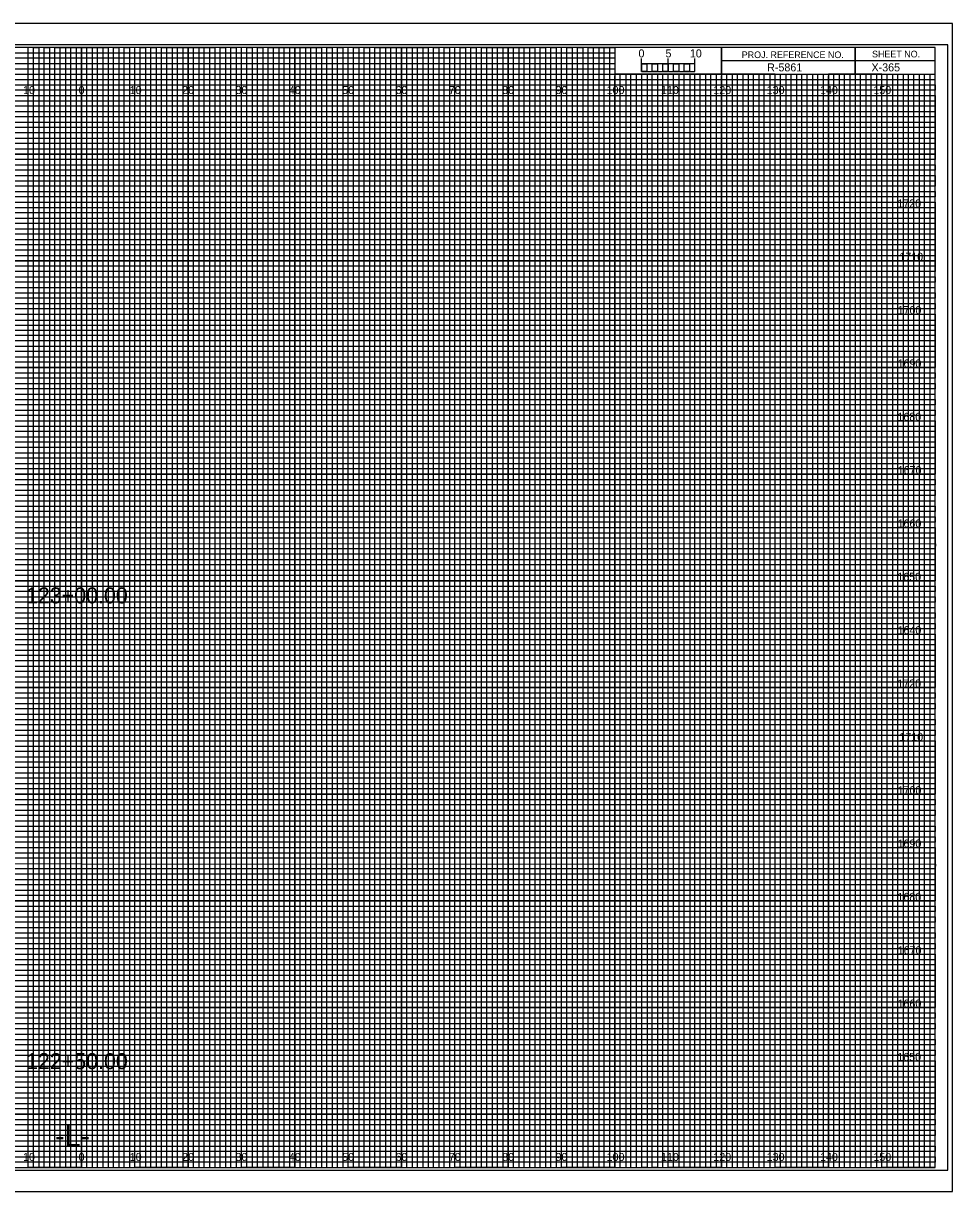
# Model space of a CAD drawing. Extents: x -13 to 323, y -5 to 2414.
# Drawn here: x 149.1 to 323.3, y 215.5 to 434.5 of the extents above; entities that cross this region are included whole.
import ezdxf

# ---------------------------------------------------------------- set-up
doc = ezdxf.new("R2010")
doc.units = 0
for name, color, linetype in [('Prop XS Alignment Label', 7, 'Continuous'), ('Prop XS Bar Scale Labels', 7, 'Continuous'), ('Prop XS Elevation Labels', 7, 'Continuous'), ('Prop XS Offset Labels', 7, 'Continuous'), ('Prop XS Project Number', 7, 'Continuous'), ('Prop XS Sheet Number', 7, 'Continuous'), ('Prop XS Station Labels', 7, 'Continuous'), ('Sheet Cross Section CELL', 7, 'Continuous'), ('Sheet Cross Section Grid Major CELL', 7, 'Continuous'), ('Sheet Cross Section Grid Middle CELL', 7, 'Continuous'), ('Sheet Cross Section Grid Minor 1 CELL', 7, 'Continuous'), ('Sheet Cross Section Grid Minor 2 CELL', 7, 'Continuous'), ('Sheet Cross Section Scale CELL', 7, 'Continuous'), ('Sheet Cutting Line CELL', 7, 'Continuous'), ('Sheet DOT Grid CELL', 7, 'Continuous'), ('Sheet Plot Border Inside CELL', 7, 'Continuous'), ('Sheet Plot Border Outside CELL', 7, 'Continuous')]:
    doc.layers.add(name, color=color, linetype=linetype)

msp = doc.modelspace()

# ---------------------------------------------------------------- linework, layer by layer
at = {"layer": 'Sheet Cross Section CELL'}
for p, q in [((305, 430), (305, 425)), ((305, 425), (305, 430)), ((280, 427.5), (280, 425)), ((320, 427.49), (280, 427.49)), ((280, 425), (320, 425))]:
    msp.add_line(p, q, dxfattribs=at)
for points in [[(320, 430), (0, 430), (0, 220), (320, 220)], [(280, 430), (260, 430), (260, 425.03), (280, 425.03)], [(320, 430), (280, 430), (280, 425), (320, 425)]]:
    msp.add_lwpolyline(points, close=True, dxfattribs=at)
at = {"layer": 'Sheet Cross Section Grid Major CELL'}
for p, q in [((150, 430), (140, 430)), ((150, 220), (150, 430)), ((170, 430), (160, 430)), ((160, 430), (160, 220)), ((170, 220), (170, 430)), ((190, 430), (180, 430)), ((180, 430), (180, 220)), ((190, 220), (190, 430)), ((210, 430), (200, 430)), ((200, 430), (200, 220)), ((210, 220), (210, 430)), ((230, 430), (220, 430)), ((220, 430), (220, 220)), ((230, 220), (230, 430)), ((250, 430), (240, 430)), ((240, 430), (240, 220)), ((250, 220), (250, 430)), ((260, 430), (260, 220)), ((270, 220), (270, 425)), ((290, 425), (280, 425)), ((280, 425), (280, 220)), ((290, 220), (290, 425)), ((310, 425), (300, 425)), ((300, 425), (300, 220)), ((310, 220), (310, 425)), ((160, 220), (150, 220)), ((180, 220), (170, 220)), ((200, 220), (190, 220)), ((220, 220), (210, 220)), ((240, 220), (230, 220)), ((260, 220), (250, 220)), ((280, 220), (270, 220)), ((300, 220), (290, 220)), ((320, 220), (310, 220)), ((320, 220), (320, 220))]:
    msp.add_line(p, q, dxfattribs=at)
for points in [[(0, 420), (320, 420), (320, 410), (0, 410)], [(0, 400), (320, 400), (320, 390), (0, 390)], [(0, 380), (320, 380), (320, 370), (0, 370)], [(0, 360), (320, 360), (320, 350), (0, 350)], [(0, 340), (320, 340), (320, 330), (0, 330)], [(0, 320), (320, 320), (320, 310), (0, 310)], [(0, 300), (320, 300), (320, 290), (0, 290)], [(0, 280), (320, 280), (320, 270), (0, 270)], [(0, 260), (320, 260), (320, 250), (0, 250)], [(0, 240), (320, 240), (320, 230), (0, 230)]]:
    msp.add_lwpolyline(points, dxfattribs=at)
at = {"layer": 'Sheet Cross Section Grid Middle CELL'}
for points in [[(145, 220), (155, 220), (155, 430), (165, 430), (165, 220), (175, 220), (175, 430), (185, 430), (185, 220), (195, 220), (195, 430), (205, 430), (205, 220), (215, 220), (215, 430), (225, 430), (225, 220), (235, 220), (235, 430), (245, 430), (245, 220), (255, 220), (255, 430), (259.93, 430), (260, 430), (260, 425), (264.99, 425), (264.99, 220), (275, 220), (275, 425), (285, 425), (285, 220), (295, 220), (295, 425), (305, 425), (305, 220), (315, 220), (315, 425)], [(0, 425), (275, 425)], [(0, 405), (320, 405), (320, 415), (0, 415)], [(0, 385), (320, 385), (320, 395), (0, 395)], [(0, 365), (320, 365), (320, 375), (0, 375)], [(0, 345), (320, 345), (320, 355), (0, 355)], [(0, 325), (320, 325), (320, 335), (0, 335)], [(0, 305), (320, 305), (320, 315), (0, 315)], [(0, 285), (320, 285), (320, 295), (0, 295)], [(0, 265), (320, 265), (320, 275), (0, 275)], [(0, 245), (320, 245), (320, 255), (0, 255)], [(0, 225), (320, 225), (320, 235), (0, 235)]]:
    msp.add_lwpolyline(points, dxfattribs=at)
at = {"layer": 'Sheet Cross Section Grid Minor 1 CELL'}
for p, q in [((0, 429), (260, 429)), ((260, 427.98), (0, 427.98)), ((260, 429), (260, 427.98)), ((0, 427), (260, 427)), ((260, 425.89), (0, 425.89)), ((260, 427), (260, 425.89)), ((0, 424), (320, 424))]:
    msp.add_line(p, q, dxfattribs=at)
for points in [[(0, 423), (270, 423), (320, 423), (320, 422), (0, 422)], [(0, 421), (320, 421), (320, 419), (0, 419)], [(0, 418), (320, 418), (320, 417), (0, 416.98)], [(0, 416), (320, 416), (320, 414), (0, 414)], [(0, 413), (320, 413), (320, 412), (0, 412)], [(0, 411), (320, 411), (320, 409), (0, 409)], [(0, 408), (320, 408), (320, 407), (0, 407)], [(0, 406), (320, 406), (320, 404), (0, 404)], [(0, 403), (320, 403), (320, 402), (0, 402)], [(0, 401), (320, 401), (320, 399), (0, 399)], [(0, 398), (320, 398), (320, 397), (0, 397)], [(0, 396), (320, 396), (320, 393.95), (320, 393), (320, 392), (0, 392)], [(0, 394), (320, 394), (320, 393), (0, 393)], [(0, 391), (320, 391), (320, 389), (0, 389.03)], [(0, 389.03), (320, 389), (320, 388), (0, 388)], [(0, 387), (320, 387), (320, 386), (0, 386)], [(0, 384), (320, 384), (320, 383), (0, 383)], [(0, 382), (320, 382), (320, 381), (0, 381)], [(-0.07, 378.89), (320, 378.89), (320, 377.88), (-0.07, 377.88)], [(0, 377), (320, 377), (320, 376), (0, 376)], [(0, 374), (320, 374), (320, 373), (0, 373)], [(0, 372), (320, 372), (320, 371), (0, 371)], [(0, 369), (320, 369), (320, 368), (0, 368)], [(0, 367), (320, 367), (320, 366), (0, 366)], [(0, 364), (320, 364), (320, 363), (0, 363)], [(0, 362), (320, 362), (320, 361), (0, 361)], [(0, 359), (320, 359), (319.99, 357.98), (0, 358)], [(0, 357), (320, 357), (320, 356), (0, 356)], [(0, 354), (320, 354), (320, 353), (0, 353)], [(0, 352), (320, 352), (320, 351), (0, 351)], [(0, 349), (320, 349), (320, 348), (0, 348)], [(0, 347), (320, 347), (320, 346), (0, 346)], [(0, 344), (320, 344), (320, 343), (0, 343)], [(0, 342), (320, 342), (320, 341), (0, 341)], [(0, 339), (320, 339), (320, 338), (0, 338)], [(0, 336.99), (320.07, 336.91), (320, 336), (0, 336)], [(0, 334), (320, 334), (320, 333), (0, 333)], [(0, 332), (320, 332), (320, 331), (0, 331)], [(0, 329), (320, 329), (320, 328), (0, 328)], [(0, 327), (320, 327), (320, 326), (0, 326)], [(0, 324), (320, 324), (320, 323), (0, 323)], [(0, 322), (320, 322), (320, 321), (0, 321)], [(0, 319), (320, 319), (320, 318), (0, 318)], [(0, 317), (320, 317), (320, 316), (0, 316)], [(0, 314), (320, 314), (320, 313), (0, 313)], [(0, 312), (320, 312), (320, 311), (0, 311)], [(0, 309), (320, 309), (320, 308), (0, 308)], [(0, 307), (320, 307), (320, 306), (0, 306)], [(0, 304), (320, 304), (320, 303), (0, 303)], [(0, 302), (320, 302), (320, 301), (0, 301)], [(0, 299), (320, 299), (319.99, 297.98), (0, 298)], [(0, 297), (320, 297), (320, 296), (0, 296)], [(0, 294), (320, 294), (320, 293), (0, 293)], [(0, 292), (320, 292), (320, 291), (0, 291)], [(0, 289), (320, 289), (320, 288), (0, 288)], [(0, 287), (320, 287), (320, 286), (0, 286)], [(0, 284), (320, 284), (320, 283), (0, 283)], [(0, 282), (320, 282), (320, 281), (0, 281)], [(0, 279), (320, 279), (320, 278), (0, 278)], [(0, 276.99), (320.07, 276.91), (320, 276), (0, 276)], [(0, 274), (320, 274), (320, 273), (0, 273)], [(0, 272), (320, 272), (320, 271), (0, 271)], [(0, 269), (320, 269), (320, 268), (0, 268)], [(0, 267), (320, 267), (320, 266), (0, 266)], [(0, 264), (320, 264), (320, 263), (0, 263)], [(0, 262), (320, 262), (320, 261), (0, 261)], [(0, 259), (320, 259), (320, 258), (0, 258)], [(0, 257), (320, 257), (320, 256), (0, 256)], [(0, 254), (320, 254), (320, 253), (0, 253)], [(0, 252), (320, 252), (320, 251), (0, 251)], [(0, 249), (320, 249), (320, 248), (0, 248)], [(0, 247), (320, 247), (320, 246), (0, 246)], [(0, 244), (320, 244), (320, 243), (0, 243)], [(0, 242), (320, 242), (320, 241), (0, 241)], [(0, 239), (320, 239), (320, 238), (0, 238)], [(0, 237), (320, 237), (320, 236), (0, 236)], [(0, 234), (320, 234), (320, 233), (0, 233)], [(0, 232), (320, 232), (320, 231), (0, 231)], [(0, 229), (320, 229), (320, 228), (0, 228)], [(0, 227), (320, 227), (320, 226), (0, 226)], [(0, 224), (320, 224), (320, 223), (0, 223)], [(0, 222), (320, 222), (320, 221), (0, 221)]]:
    msp.add_lwpolyline(points, dxfattribs=at)
at = {"layer": 'Sheet Cross Section Grid Minor 2 CELL'}
for p, q in [((267, 425), (266.01, 425)), ((266.01, 425), (266.01, 220)), ((267, 220), (267, 425)), ((269, 425), (268, 425)), ((268, 425), (268, 220)), ((269, 220), (269, 425)), ((266.01, 220), (265, 220)), ((268, 220), (267, 220))]:
    msp.add_line(p, q, dxfattribs=at)
for points in [[(150, 220), (151, 220), (151, 430), (152, 430), (152, 220)], [(152, 220), (153, 220), (153, 430), (154, 430), (154, 220)], [(155, 220), (156, 220), (156, 430), (157, 430), (157, 220)], [(157, 220), (158, 220), (158, 430), (159, 430), (159, 220)], [(160, 220), (161, 220), (161, 430), (162, 430), (162, 220)], [(162, 220), (163, 220), (163, 430), (164, 430), (164, 220)], [(165, 220), (166, 220), (166, 430), (167, 430), (167, 220)], [(167, 220), (168, 220), (168, 430), (169, 430), (169, 220)], [(170, 220), (171, 220), (171, 430), (172, 430), (172, 220)], [(172, 220), (173, 220), (173, 430), (174, 430), (174, 220)], [(175, 220), (176, 220), (176, 430), (177, 430), (177, 220)], [(177, 220), (178, 220), (178, 430), (179, 430), (179, 220)], [(180, 220), (181, 220), (181, 430), (182, 430), (182, 220)], [(182, 220), (183, 220), (183, 430), (184, 430), (184, 220)], [(185, 220), (186, 220), (186, 430), (187, 430), (187, 220)], [(187, 220), (188, 220), (188, 430), (189, 430), (189, 220)], [(190, 220), (191, 220), (191, 430), (192, 430), (192, 220)], [(192, 220), (193, 220), (193, 430), (194, 430), (194, 220)], [(195, 220), (196, 220), (196, 430), (197, 430), (197, 220)], [(197, 220), (198, 220), (198, 430), (199, 430), (199, 220)], [(200, 220), (201, 220), (201, 430), (202, 430), (202, 220)], [(202, 220), (203, 220), (203, 430), (204, 430), (204, 220)], [(205, 220), (206, 220), (206, 430), (207, 430), (207, 220)], [(207, 220), (208, 220), (208, 430), (209, 430), (209, 220)], [(210, 220), (211, 220), (211, 430), (212, 430), (212, 220)], [(212, 220), (213, 220), (213, 430), (214, 430), (214, 220)], [(215, 220), (216, 220), (216, 430), (217, 430), (217, 220)], [(217, 220), (218, 220), (218, 430), (219, 430), (219, 220)], [(220, 220), (221, 220), (221, 430), (222, 430), (222, 220)], [(222, 220), (223, 220), (223, 430), (224, 430), (224, 220)], [(225, 220), (226, 220), (226, 430), (227, 430), (227, 220)], [(227, 220), (228, 220), (228, 430), (229, 430), (229, 220)], [(230, 220), (231, 220), (231, 430), (232, 430), (232, 220)], [(232, 220), (233, 220), (233, 430), (234, 430), (234, 220)], [(235, 220), (236, 220), (236, 430), (237, 430), (237, 220)], [(237, 220), (238, 220), (238, 430), (239, 430), (239, 220)], [(240, 220), (241, 220), (241, 430), (242, 430), (242, 220)], [(242, 220), (243, 220), (243, 430), (244, 430), (244, 220)], [(245, 220), (246, 220), (246, 430), (247, 430), (247, 220)], [(247, 220), (248, 220), (248, 430), (249, 430), (249, 220)], [(250, 220), (251, 220), (251, 430), (252, 430), (252, 220)], [(252, 220), (253, 220), (253, 430), (254, 430), (254, 220)], [(255, 220), (256, 220), (256, 430), (257, 430), (257, 220)], [(257, 220), (258, 220), (258, 430), (259, 430), (259, 220)], [(260, 220), (261, 220), (261, 425), (262.02, 425), (262.02, 220)], [(262, 220), (263, 220), (263, 425), (263.99, 425), (263.99, 220)], [(270, 220), (270.98, 220), (270.98, 425), (272, 425), (272, 220)], [(272, 220), (273, 220), (273, 425), (274.05, 425), (274.05, 220)], [(275, 220), (276, 220), (276, 425), (277, 425), (277, 220)], [(277, 220), (278, 220), (278, 425), (279, 425), (279, 220)], [(280, 220), (281, 220), (281, 425), (282, 425), (282, 220)], [(282, 220), (283, 220), (283, 425), (284, 425), (284, 220)], [(285, 220), (286, 220), (286, 425), (287, 425), (287, 220)], [(287, 220), (288, 220), (288, 425), (289, 425), (289, 220)], [(290, 220), (291, 220), (291, 425), (292, 425), (292, 220)], [(292, 220), (293, 220), (293, 425), (294, 425), (294, 220)], [(295, 220), (296, 220), (296, 425), (297, 425), (297, 220)], [(297, 220), (298, 220), (298, 425), (299, 425), (299, 220)], [(300, 220), (301, 220), (301, 425), (302, 425), (302, 220)], [(302, 220), (303, 220), (303, 425), (304, 425), (304, 220)], [(305, 220), (306, 220), (306, 425), (307, 425), (307, 220)], [(307, 220), (308, 220), (308, 425), (309, 425), (309, 220)], [(310, 220), (311, 220), (311, 425), (312, 425), (312, 220)], [(312, 220), (313, 220), (313, 425), (314, 425), (314, 220)], [(315, 220), (316, 220), (316, 425), (317, 425), (317, 220)], [(317, 220), (318, 220), (318, 425), (319, 425), (319, 220)]]:
    msp.add_lwpolyline(points, dxfattribs=at)
at = {"layer": 'Sheet Cross Section Scale CELL'}
for p, q in [((265, 425.49), (265, 427.9)), ((265, 426.9), (265, 427.9)), ((270, 425.49), (270, 427.9)), ((275, 425.49), (275, 427.9)), ((275, 426.9), (275, 427.9))]:
    msp.add_line(p, q, dxfattribs=at)
for points in [[(275, 426.9), (265, 426.9), (265, 425.49), (275, 425.49)], [(265, 426.9), (266, 426.9), (266, 425.49), (265, 425.49)], [(267, 426.9), (268, 426.9), (268, 425.49), (267, 425.49)], [(269, 426.9), (270, 426.9), (270, 425.49), (269, 425.49)], [(271, 426.9), (272, 426.9), (272, 425.49), (271, 425.49)], [(273, 426.9), (274, 426.9), (274, 425.49), (273, 425.49)]]:
    msp.add_lwpolyline(points, close=True, dxfattribs=at)
at = {"layer": 'Sheet Cutting Line CELL'}
for p, q in [((323.3, 434.5), (-13.4, 434.5)), ((-13.4, 215.5), (323.3, 215.5))]:
    msp.add_line(p, q, dxfattribs=at)
at = {"layer": 'Sheet DOT Grid CELL'}
for p, q in [((150, 220), (150, 430)), ((160, 220), (160, 430)), ((170, 220), (170, 430)), ((180, 220), (180, 430)), ((190, 220), (190, 430)), ((200, 220), (200, 430)), ((210, 220), (210, 430)), ((220, 220), (220, 430)), ((230, 220), (230, 430)), ((240, 220), (240, 430)), ((250, 220), (250, 430)), ((260, 220), (260, 424.69)), ((270, 220), (270, 424.69)), ((280, 220), (280, 424.69)), ((290, 220), (290, 424.69)), ((300, 220), (300, 424.69)), ((310, 220), (310, 424.69)), ((0, 420), (320, 420)), ((0, 410), (320, 410)), ((0, 400), (320, 400)), ((0, 390), (320, 390)), ((0, 380), (320, 380)), ((0, 370), (320, 370)), ((0, 360), (320, 360)), ((0, 350), (320, 350)), ((0, 340), (320, 340)), ((0, 330), (320, 330)), ((0, 320), (320, 320)), ((0, 310), (320, 310)), ((0, 300), (320, 300)), ((0, 290), (320, 290)), ((0, 280), (320, 280)), ((0, 270), (320, 270)), ((0, 260), (320, 260)), ((0, 250), (320, 250)), ((0, 240), (320, 240)), ((0, 230), (320, 230))]:
    msp.add_line(p, q, dxfattribs=at)
at = {"layer": 'Sheet Plot Border Inside CELL'}
msp.add_lwpolyline([(-10.8, 219.5), (322.4, 219.5), (322.4, 430.5), (-10.8, 430.5)], close=True, dxfattribs=at)
at = {"layer": 'Sheet Plot Border Outside CELL'}
msp.add_lwpolyline([(-13.4, 215.5), (323.3, 215.5), (323.3, 434.5), (-13.4, 434.5)], close=True, dxfattribs=at)

# ---------------------------------------------------------------- texts
at = {"layer": 'Prop XS Alignment Label'}
msp.add_text('-L-', height=4, dxfattribs=at).set_placement((155.06, 224))
at = {"layer": 'Prop XS Bar Scale Labels'}
for s, p in [('5', (269.47, 428.12)), ('10', (274.04, 428.12))]:
    msp.add_text(s, height=1.5, dxfattribs=at).set_placement(p)
at = {"layer": 'Prop XS Elevation Labels'}
for s, p in [('1720', (312.93, 400)), ('1710', (313.31, 390)), ('1700', (312.98, 380)), ('1690', (312.97, 370)), ('1680', (312.95, 360)), ('1670', (313, 350)), ('1660', (312.97, 340)), ('1650', (312.92, 330)), ('1640', (312.97, 320)), ('1720', (312.93, 310)), ('1710', (313.31, 300)), ('1700', (312.98, 290)), ('1690', (312.97, 280)), ('1680', (312.95, 270)), ('1670', (313, 260)), ('1660', (312.97, 250)), ('1650', (312.92, 240))]:
    msp.add_text(s, height=1.5, dxfattribs=at).set_placement(p)
at = {"layer": 'Prop XS Offset Labels'}
for s, p in [('10', (149.04, 421.25)), ('0', (159.45, 421.25)), ('0', (159.45, 421.25)), ('10', (169.04, 421.25)), ('20', (178.86, 421.25)), ('30', (188.86, 421.25)), ('40', (198.86, 421.25)), ('50', (208.86, 421.25)), ('60', (218.86, 421.25)), ('70', (228.86, 421.25)), ('80', (238.86, 421.25)), ('90', (248.86, 421.25)), ('100', (258.44, 421.25)), ('110', (268.62, 421.25)), ('120', (278.44, 421.25)), ('130', (288.44, 421.25)), ('140', (298.44, 421.25)), ('150', (308.44, 421.25)), ('10', (149.04, 221.25)), ('0', (159.45, 221.25)), ('0', (159.45, 221.25)), ('10', (169.04, 221.25)), ('20', (178.86, 221.25)), ('30', (188.86, 221.25)), ('40', (198.86, 221.25)), ('50', (208.86, 221.25)), ('60', (218.86, 221.25)), ('70', (228.86, 221.25)), ('80', (238.86, 221.25)), ('90', (248.86, 221.25)), ('100', (258.44, 221.25)), ('110', (268.62, 221.25)), ('120', (278.44, 221.25)), ('130', (288.44, 221.25)), ('140', (298.44, 221.25)), ('150', (308.44, 221.25))]:
    msp.add_text(s, height=1.5, dxfattribs=at).set_placement(p)
at = {"layer": 'Prop XS Project Number'}
msp.add_text('R-5861', height=1.5, dxfattribs=at).set_placement((288.53, 425.5))
at = {"layer": 'Prop XS Sheet Number'}
msp.add_text('X-365', height=1.5, dxfattribs=at).set_placement((308.09, 425.5))
at = {"layer": 'Prop XS Station Labels'}
for s, p in [('123+00.00', (149.59, 325.77)), ('122+50.00', (149.59, 238.46))]:
    msp.add_text(s, height=3, dxfattribs=at).set_placement(p)
at = {"layer": 'Sheet Cross Section CELL'}
for s, p in [('PROJ. REFERENCE NO.', (283.77, 427.99)), ('SHEET NO.', (308.19, 428.12))]:
    msp.add_text(s, height=1.25, dxfattribs=at).set_placement(p)
at = {"layer": 'Sheet Cross Section Scale CELL'}
msp.add_text('0', height=1.5, dxfattribs=at).set_placement((264.41, 428.12))

doc.saveas('drawing.dxf')
